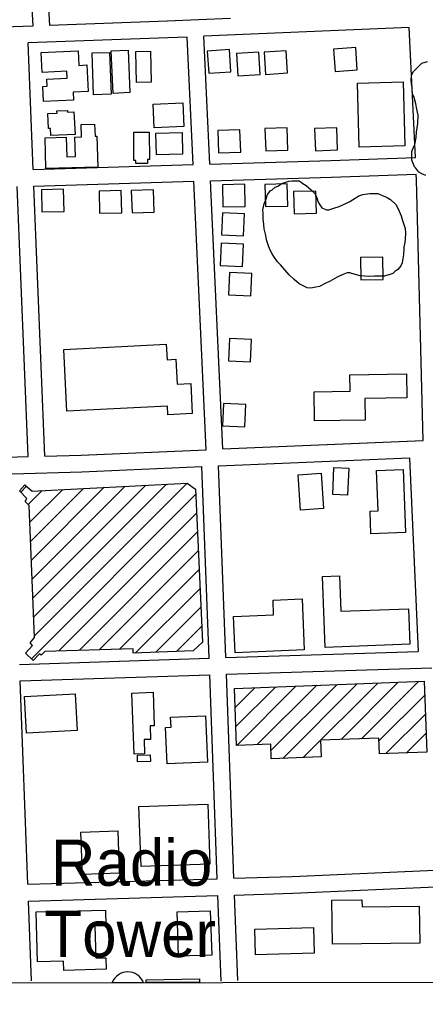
# Model space of a CAD drawing. Extents: x 3313447 to 3351316, y 703786 to 729172.
# Drawn here: x 3327294 to 3328024, y 709166 to 710910 of the extents above; entities that cross this region are included whole.
import ezdxf

# ---------------------------------------------------------------- set-up
doc = ezdxf.new("R2010")
doc.units = 0
for name, color, linetype in [('V-BLDG-OTLN', 7, 'Continuous'), ('V-GRID-FRAM', 7, 'Continuous'), ('V-ROAD-CNTR', 7, 'Continuous'), ('V-SITE-VEGE', 7, 'Continuous'), ('V-TOPO-TOWR', 7, 'Continuous'), ('V-TOPO-TOWR-IDEN', 7, 'Continuous')]:
    doc.layers.add(name, color=color, linetype=linetype)

msp = doc.modelspace()

# ---------------------------------------------------------------- linework, layer by layer
at = {"layer": 'V-BLDG-OTLN'}
for p, q in [((3327296, 710060.9), (3327306.6, 710071.5)), ((3327309.6, 710039.1), (3327334.4, 710063.9)), ((3327312.7, 710006.9), (3327371.6, 710065.8)), ((3327314, 709972.8), (3327408.9, 710067.7)), ((3327315.3, 709938.8), (3327446.2, 710069.7)), ((3327316.6, 709904.7), (3327483.5, 710071.6)), ((3327317.9, 709870.7), (3327520.7, 710073.5)), ((3327319.2, 709836.6), (3327558, 710075.4)), ((3327320.5, 709802.5), (3327595.2, 710077.2)), ((3327315.2, 709761.9), (3327610.5, 710057.2)), ((3327364.5, 709775.8), (3327612, 710023.4)), ((3327400.9, 709776.9), (3327613.6, 709989.6)), ((3327437.3, 709777.9), (3327615.2, 709955.8)), ((3327473.7, 709779), (3327616.7, 709922)), ((3327502, 709771.9), (3327618.3, 709888.2)), ((3327538.8, 709773.4), (3327619.8, 709854.4)), ((3327575.7, 709774.9), (3327621.4, 709820.6)), ((3327684.2, 709606.1), (3327790.5, 709712.5)), ((3327721, 709607.6), (3327827.3, 709713.9)), ((3327745.8, 709597), (3327864.1, 709715.3)), ((3327767.1, 709583), (3327900.8, 709716.7)), ((3327803.9, 709584.4), (3327937.6, 709718.1)), ((3327871.6, 709616.8), (3327974.4, 709719.5)), ((3327908.4, 709618.2), (3328011.1, 709720.9)), ((3327681.5, 709674.2), (3327717, 709709.6)), ((3327682.8, 709640.1), (3327753.8, 709711)), ((3327939.8, 709614.3), (3328022, 709696.4)), ((3327952.4, 709591.5), (3328023.3, 709662.4)), ((3327989.2, 709592.9), (3328024.6, 709628.3)), ((3327521.3, 709185), (3327617.4, 709186.9)), ((3327521.3, 709180.4), (3327521.3, 709185)), ((3327617.5, 709180.6), (3327521.3, 709180.4)), ((3327617.4, 709186.9), (3327617.5, 709180.6))]:
    msp.add_line(p, q, dxfattribs=at)
for points in [[(3327332.9, 710850.2), (3327399.3, 710853.2), (3327400.5, 710827.3), (3327415, 710828), (3327417.2, 710780.1), (3327390.5, 710778.9), (3327391.1, 710765.1), (3327337, 710762.6), (3327335.8, 710789.5), (3327343.5, 710789.9), (3327342.9, 710802.8), (3327379.8, 710804.5), (3327379.2, 710816.7), (3327334.5, 710814.7)], [(3327427, 710774.6), (3327424.5, 710849.7), (3327455.9, 710850.7), (3327458.4, 710775.6)], [(3327489, 710854.7), (3327492.3, 710778.4), (3327462, 710777.1), (3327458.8, 710853.4)], [(3327529, 710853), (3327530.2, 710797.1), (3327504.3, 710796.6), (3327503.1, 710852.4)], [(3327671.3, 710855.6), (3327631.4, 710853.1), (3327633.9, 710813.2), (3327673.8, 710815.7)], [(3327723.8, 710850.9), (3327683.9, 710848.4), (3327686.4, 710808.5), (3327726.3, 710811)], [(3327773.2, 710853.6), (3327733.3, 710851.1), (3327735.8, 710811.2), (3327775.7, 710813.7)], [(3327898.3, 710859.1), (3327858.4, 710856.6), (3327860.9, 710816.6), (3327900.9, 710819.2)], [(3327901.5, 710795.5), (3327983.6, 710797.6), (3327986.5, 710682.8), (3327904.4, 710680.7)], [(3327534, 710757.8), (3327587.5, 710759.8), (3327589.1, 710717.4), (3327535.6, 710715.4)], [(3327393.7, 710703.4), (3327350.4, 710701.2), (3327349.8, 710714.1), (3327345.9, 710713.9), (3327344.5, 710740.7), (3327361.3, 710741.5), (3327361.1, 710745.4), (3327380.2, 710746.3), (3327380.4, 710743.3), (3327391.7, 710743.8)], [(3327434.5, 710644.7), (3327341.4, 710641.9), (3327339.8, 710697.3), (3327377.9, 710698.5), (3327379, 710662.9), (3327394.3, 710663.4), (3327393.2, 710698.6), (3327405.4, 710699), (3327404.7, 710721.2), (3327428.9, 710721.9), (3327429.6, 710700), (3327432.8, 710700.1)], [(3327499.2, 710656.5), (3327499.1, 710707.2), (3327527.1, 710707.2), (3327527.2, 710658.1), (3327523.6, 710658.1), (3327523.6, 710651.2), (3327502.8, 710651.1), (3327502.7, 710656.5)], [(3327539.8, 710666.5), (3327538.8, 710705.5), (3327585.9, 710706.7), (3327586.9, 710667.8)], [(3327651.6, 710670.2), (3327691.5, 710671.6), (3327690.1, 710711.6), (3327650.2, 710710.2)], [(3327736.3, 710673.7), (3327776.3, 710675.1), (3327774.9, 710715.1), (3327734.9, 710713.7)], [(3327825.6, 710674), (3327865.6, 710675.5), (3327864.2, 710715.4), (3327824.2, 710714)], [(3327333.2, 710604.1), (3327334.3, 710564.1), (3327374.3, 710565.2), (3327373.2, 710605.2)], [(3327476.8, 710602.6), (3327436.8, 710601.7), (3327437.7, 710561.7), (3327477.6, 710562.6)], [(3327534.6, 710603.9), (3327494.6, 710602.4), (3327496.1, 710562.5), (3327536, 710563.9)], [(3327698.6, 710613.9), (3327658.6, 710613), (3327659.5, 710573.1), (3327699.5, 710573.9)], [(3327774.9, 710614.5), (3327734.9, 710613.6), (3327735.8, 710573.6), (3327775.8, 710574.5)], [(3327826.4, 710601.7), (3327786.4, 710600.8), (3327787.3, 710560.8), (3327827.3, 710561.7)], [(3327658.5, 710562.8), (3327656.7, 710522.9), (3327696.6, 710521.1), (3327698.4, 710561)], [(3327656.3, 710507.8), (3327654.5, 710467.8), (3327694.5, 710466), (3327696.3, 710506)], [(3327947.1, 710442.7), (3327946.5, 710482.7), (3327906.5, 710482.1), (3327907.1, 710442.1)], [(3327671.5, 710455.2), (3327669.7, 710415.3), (3327709.6, 710413.5), (3327711.4, 710453.4)], [(3327373.6, 710317.3), (3327557.7, 710326.5), (3327559.1, 710298.8), (3327574.8, 710299.6), (3327577.1, 710254.8), (3327601.5, 710256), (3327604.1, 710202.2), (3327560.7, 710200), (3327559.9, 710215.2), (3327379.2, 710206.1)], [(3327671, 710336.9), (3327669.2, 710297), (3327709.2, 710295.2), (3327711, 710335.1)], [(3327915.1, 710190.5), (3327824, 710189.1), (3327823.2, 710241.3), (3327888.1, 710242.3), (3327887.7, 710271.7), (3327989.1, 710273.2), (3327989.7, 710230.3), (3327914.5, 710229.2)], [(3327660.4, 710220.1), (3327658.6, 710180.1), (3327698.6, 710178.3), (3327700.4, 710218.3)], [(3327885.7, 710104.2), (3327883.4, 710055.3), (3327856.7, 710056.5), (3327859, 710105.4)], [(3327983.4, 710101.7), (3327987.3, 709988.6), (3327925.5, 709986.4), (3327924.1, 710026.7), (3327938.1, 710027.2), (3327935.5, 710100.1)], [(3327835.9, 710095), (3327840.4, 710031.8), (3327799.1, 710028.9), (3327794.7, 710092.1)], [(3327610.1, 710066.6), (3327622.7, 709791.7), (3327606.1, 709776.1), (3327498.3, 709771.8), (3327498.3, 709779.7), (3327339.6, 709775.1), (3327332.6, 709768.2), (3327330.1, 709770.5), (3327318.4, 709758.8), (3327304.4, 709772.1), (3327317.1, 709785.9), (3327312.9, 709790.7), (3327320.6, 709800), (3327311.5, 710037.3), (3327304, 710044.4), (3327306.9, 710049.4), (3327293.7, 710063.3), (3327303.2, 710074.4), (3327316.6, 710063), (3327595, 710077.3)], [(3327995.3, 709788), (3327843, 709782.3), (3327838.3, 709909.5), (3327869, 709910.6), (3327871.4, 709847.1), (3327992.9, 709851.6)], [(3327805.4, 709777.6), (3327681.2, 709772.7), (3327678.7, 709837.6), (3327750.6, 709840.4), (3327749.5, 709867.3), (3327801.8, 709869.4)], [(3327680.2, 709708.2), (3328021, 709721.3), (3328025.9, 709594.3), (3327940.7, 709591), (3327939.6, 709619.4), (3327834.9, 709615.4), (3327836.1, 709585.7), (3327746.4, 709582.2), (3327745.4, 709608.5), (3327684.1, 709606.1)], [(3327397.3, 709633.1), (3327306.2, 709628.4), (3327302.8, 709694.3), (3327393.9, 709698.9)], [(3327500, 709590.7), (3327496, 709700.3), (3327533.9, 709701.7), (3327536.1, 709641.4), (3327528.4, 709641.1), (3327529.2, 709617), (3327517.8, 709616.6), (3327518.7, 709591.3)], [(3327631.9, 709576.2), (3327559.3, 709572.9), (3327556.3, 709638.2), (3327566.2, 709638.7), (3327565.4, 709656.7), (3327628.1, 709659.6)], [(3327506.2, 709576.8), (3327505.9, 709588.6), (3327528.9, 709589.1), (3327529.2, 709577.2)], [(3327512.3, 709388.6), (3327508.6, 709496.3), (3327632.3, 709500.5), (3327635.9, 709392.8)], [(3327404.3, 709450.4), (3327470.6, 709452.7), (3327473.1, 709376.7), (3327406.8, 709374.5)], [(3328013.2, 709251.1), (3327856.1, 709249.1), (3327855.1, 709328.5), (3327909.3, 709329.2), (3327909.5, 709316.2), (3328012.3, 709317.5)], [(3327323.8, 709307.2), (3327448.5, 709310.6), (3327449.3, 709282.1), (3327429.5, 709281.6), (3327431.1, 709224.6), (3327449.3, 709225.1), (3327449.8, 709204.2), (3327373.6, 709202.2), (3327373.1, 709219.1), (3327326.3, 709217.8)], [(3327579.5, 709227.6), (3327577, 709307.3), (3327636.7, 709309.1), (3327639.2, 709229.4)], [(3327823.5, 709233.3), (3327718.1, 709230.1), (3327716.7, 709276.1), (3327822.1, 709279.3)]]:
    msp.add_lwpolyline(points, close=True, dxfattribs=at)
at = {"layer": 'V-GRID-FRAM'}
msp.add_lwpolyline([(3317576.9, 727351), (3317595.4, 709166), (3349105.8, 709211.8), (3349071.4, 727396.8), (3317576.9, 727351)], dxfattribs=at)
at = {"layer": 'V-ROAD-CNTR'}
for points in [[(3327277.6, 711621.7), (3327317.8, 710897.8)], [(3327328.8, 711240.4), (3327347.8, 710898.9)], [(3327317.8, 710897.8), (3327265.2, 710895.9)], [(3327673.3, 710911.6), (3327559, 710906.7), (3327347.8, 710898.9)], [(3327994, 710895.4), (3327625.1, 710879.5)], [(3328005.3, 710662), (3327994, 710895.4)], [(3327595.1, 710878.2), (3327560.2, 710876.7), (3327309.7, 710867.5)], [(3327318.7, 710640.6), (3327309.7, 710867.5)], [(3327605.7, 710649.1), (3327595.1, 710878.2)], [(3327635.7, 710650), (3327625.1, 710879.5)], [(3327635.7, 710650), (3327853.4, 710656.5), (3328005.3, 710662)], [(3327318.7, 710640.6), (3327605.7, 710649.1)], [(3327319.9, 710610.6), (3327607.1, 710619.2)], [(3327629.4, 710137.2), (3327607.1, 710619.2)], [(3327637.1, 710620.1), (3327854.4, 710626.5), (3328006.8, 710632)], [(3327659.4, 710138.5), (3327637.1, 710620.1)], [(3328019.1, 710153.8), (3328007.2, 710622), (3328006.8, 710632)], [(3327309.3, 710124.8), (3327289.9, 710609.7)], [(3327339.3, 710125.7), (3327319.9, 710610.6)], [(3327659.4, 710138.5), (3328019.1, 710153.8)], [(3327339.3, 710125.7), (3327404.6, 710127.6), (3327629.4, 710137.2)], [(3326900.6, 710112.5), (3327309.3, 710124.8)], [(3327651.7, 710108.1), (3327994.6, 710122.8)], [(3327994.6, 710122.8), (3328010, 709775)], [(3327280.7, 710093.9), (3327405.7, 710097.6), (3327621.8, 710106.9)], [(3327634.6, 709762.9), (3327621.8, 710106.9)], [(3327664.6, 709763.9), (3327651.7, 710108.1)], [(3327664.6, 709763.9), (3328010, 709775)], [(3327293.7, 709751.8), (3327634.6, 709762.9)], [(3327294.8, 709721.9), (3327635.7, 709732.9)], [(3327649.3, 709366.7), (3327635.7, 709732.9)], [(3327665.7, 709733.9), (3328034.7, 709745.8)], [(3327679.3, 709367.6), (3327665.7, 709733.9)], [(3327308.7, 709356.8), (3327294.8, 709721.9)], [(3327679.3, 709367.6), (3327783.8, 709370.6), (3328053.7, 709382.9)], [(3327308.7, 709356.8), (3327649.3, 709366.7)], [(3327680.4, 709337.6), (3327784.9, 709340.7), (3328055, 709352.9)], [(3327309.8, 709326.8), (3327650.4, 709336.7)], [(3327656.2, 709183), (3327650.4, 709336.7)], [(3327686.2, 709184.1), (3327680.4, 709337.6)], [(3327315.2, 709183.6), (3327309.8, 709326.8)]]:
    msp.add_lwpolyline(points, dxfattribs=at)
at = {"layer": 'V-SITE-VEGE'}
msp.add_lwpolyline([(3328024.2, 710629.3), (3328016.8, 710632.3), (3328011.7, 710635.4), (3328005.9, 710642.9), (3328003.7, 710645.1), (3327998.6, 710657), (3327998.8, 710672.6), (3328001.1, 710678.5), (3328004.2, 710685.1), (3328006.6, 710697.7), (3328007.5, 710707.3), (3328009.9, 710722.9), (3328010.1, 710737.7), (3328008, 710748.8), (3328006, 710758.5), (3328003.1, 710769.6), (3328000.3, 710776.4), (3327999.6, 710783.8), (3327999.7, 710786.7), (3327998.3, 710794.2), (3327997.6, 710800.1), (3327998.5, 710809.7), (3328001.6, 710816.4), (3328016.6, 710831), (3328027, 710834.5)], dxfattribs=at)
msp.add_lwpolyline([(3327921.6, 710448.3), (3327905.9, 710449.7), (3327897.2, 710451.6), (3327887.6, 710454.7), (3327882.5, 710454.8), (3327873.5, 710451.2), (3327864.6, 710446.9), (3327851.9, 710439.6), (3327844.4, 710436), (3327833.2, 710430.3), (3327826.5, 710428.9), (3327817.6, 710427.5), (3327810.9, 710427.6), (3327796.2, 710435.2), (3327787.4, 710442.7), (3327778.6, 710451), (3327762.6, 710469), (3327757.4, 710474.3), (3327750.9, 710484), (3327748, 710489.2), (3327743.7, 710496.7), (3327741.5, 710503.4), (3327738, 710513.8), (3327736.6, 710522), (3327733.8, 710533.9), (3327733.2, 710541.3), (3327731.8, 710551.7), (3327732, 710562.1), (3327731.3, 710568), (3327733.7, 710578.4), (3327736.7, 710585.8), (3327739.8, 710595.4), (3327742.1, 710598.3), (3327745.1, 710602.7), (3327747.4, 710603.4), (3327753.4, 710608.5), (3327757.8, 710610.7), (3327765.3, 710615), (3327770.5, 710617.2), (3327778, 710619.3), (3327783.2, 710620), (3327796.5, 710619.8), (3327800.2, 710617.5), (3327803.1, 710615.2), (3327809, 710611.5), (3327817.8, 710603.9), (3327825.1, 710596.4), (3327828, 710589.7), (3327830.8, 710581.5), (3327833.7, 710577), (3327837.4, 710571.8), (3327840.3, 710570.3), (3327845.5, 710568), (3327849.9, 710567.9), (3327858.8, 710570.7), (3327868.5, 710573.6), (3327881.2, 710580.1), (3327887.2, 710583), (3327896.9, 710588.8), (3327903.6, 710593.1), (3327911.1, 710595.2), (3327914.8, 710595.9), (3327923.7, 710597.3), (3327937.8, 710597.1), (3327942.2, 710595.5), (3327947.4, 710593.2), (3327954.7, 710590.2), (3327960.6, 710586.4), (3327970.1, 710577.4), (3327974.5, 710569.9), (3327979.5, 710557.2), (3327982.3, 710549), (3327986.6, 710534.2), (3327987.2, 710526), (3327987.1, 710515.6), (3327986.2, 710509), (3327984.6, 710500.8), (3327984.6, 710497.9), (3327983.7, 710487.5), (3327982.9, 710480.8), (3327981.3, 710472.7), (3327979, 710467.5), (3327973.7, 710460.9), (3327968.5, 710457.3), (3327964.7, 710453.7), (3327955.8, 710450.8), (3327952.8, 710450.1), (3327949.8, 710448.7), (3327932, 710448.9)], close=True, dxfattribs=at)
at = {"layer": 'V-TOPO-TOWR'}
msp.add_line((3327460.5, 709180.4), (3327516.5, 709180.4), dxfattribs=at)
msp.add_arc((3327488.5, 709169.6), 30, 21.2373, 158.9294, dxfattribs=at)

# ---------------------------------------------------------------- texts
at = {"layer": 'V-TOPO-TOWR-IDEN'}
for s, p in [('Radio', (3327350.4, 709354.1)), ('Tower', (3327338.7, 709226.3))]:
    msp.add_text(s, height=83, dxfattribs=at).set_placement(p)

doc.saveas('drawing.dxf')
